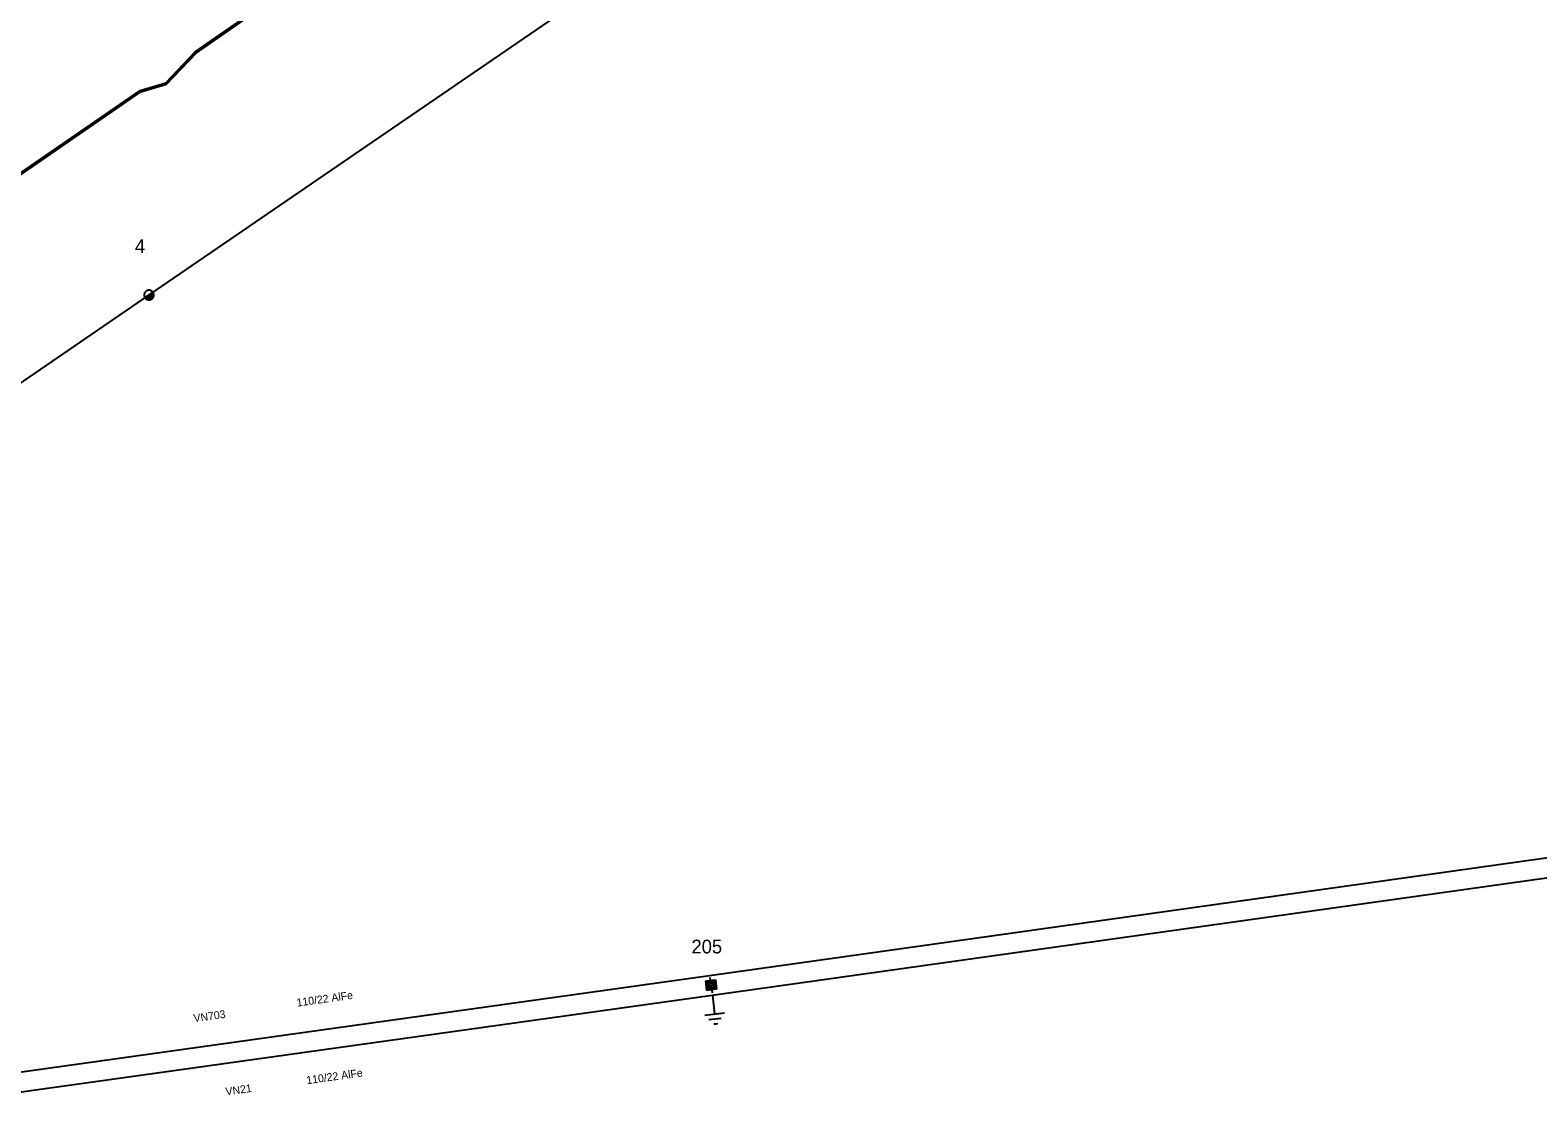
# Model space of a CAD drawing. Extents: x -545588 to -543214, y -1196037 to -1194452.
# Drawn here: x -545008.8 to -544817.1, y -1194901.6 to -1194764.6 of the extents above; entities that cross this region are included whole.
import ezdxf

# ---------------------------------------------------------------- set-up
doc = ezdxf.new("R2010")
doc.units = 0
for name, color, linetype in [('DOPLŇ_POPISY', 7, 'Continuous'), ('ELE_EON', 7, 'Continuous'), ('ELE_EON_POPIS', 7, 'Continuous'), ('POL_ZNAČKA_PRACOVNÍ', 7, 'Continuous'), ('SDEL_EON', 7, 'Continuous'), ('ZP_EON', 7, 'Continuous')]:
    doc.layers.add(name, color=color, linetype=linetype)

# ---------------------------------------------------------------- blocks, each defined once
blk = doc.blocks.new('VN440')
at = {"layer": 'ELE_EON_POPIS'}
for points in [[(1.22, 0), (1.21, 0.13), (1.19, 0.25), (1.16, 0.38), (1.11, 0.5), (1.05, 0.61), (0.98, 0.72), (0.9, 0.82), (0.81, 0.91), (0.71, 0.99), (0.6, 1.06), (0.49, 1.12), (0.37, 1.16), (0.25, 1.2), (0.12, 1.22), (-0.01, 1.22), (-0.14, 1.22), (-0.26, 1.2), (-0.39, 1.16), (-0.51, 1.12), (-0.62, 1.06), (-0.73, 0.99), (-0.83, 0.91), (-0.92, 0.82), (-1, 0.72), (-1.07, 0.61), (-1.13, 0.5), (-1.18, 0.38), (-1.21, 0.25), (-1.23, 0.13), (-1.24, 0), (-1.23, -0.13), (-1.21, -0.26), (-1.18, -0.38), (-1.13, -0.5), (-1.07, -0.62), (-1, -0.73), (-0.92, -0.83), (-0.83, -0.92), (-0.73, -1), (-0.62, -1.07), (-0.51, -1.13), (-0.39, -1.17), (-0.26, -1.2), (-0.14, -1.23), (-0.01, -1.23), (0.12, -1.23), (0.25, -1.2), (0.37, -1.17), (0.49, -1.13), (0.6, -1.07), (0.71, -1), (0.81, -0.92), (0.9, -0.83), (0.98, -0.73), (1.05, -0.62), (1.11, -0.5), (1.16, -0.38), (1.19, -0.26), (1.21, -0.13), (1.22, 0)], [(-1.24, 0), (1.22, 0)], [(-1.18, -0.34), (1.1, -0.34)], [(-1.01, -0.63), (0.97, -0.63)], [(-0.74, -0.92), (0.68, -0.92)]]:
    blk.add_lwpolyline(points, dxfattribs=at)
blk = doc.blocks.new('VN810')
at = {"layer": 'POL_ZNAČKA_PRACOVNÍ'}
for points in [[(0, -1.25), (0, -3.75)], [(1.25, -3.75), (-1.25, -3.75)], [(0.77, -4.37), (-0.8, -4.37)], [(0, -5), (-0.25, -5)], [(0.27, -5), (0, -5)]]:
    blk.add_lwpolyline(points, dxfattribs=at)
blk = doc.blocks.new('VN470')
at = {"layer": 'ELE_EON_POPIS'}
for points in [[(-1.23, 1.22), (1.23, 1.22)], [(-1.23, -1.23), (-1.23, 1.22)], [(-0.92, 0.9), (0.92, 0.9)], [(-0.92, -0.95), (-0.92, 0.9)], [(-0.61, 0.61), (0.61, 0.61)], [(-0.61, -0.62), (-0.61, 0.61)], [(-0.31, -0.27), (-0.31, 0.34)], [(-0.31, 0.34), (0.31, 0.34)], [(0, 1.22), (0, 1.97)], [(0.31, 0.34), (0.31, -0.27)], [(0.61, 0.61), (0.61, -0.62)], [(0.92, 0.9), (0.92, -0.95)], [(1.23, 1.22), (1.23, -1.23)], [(1.23, -1.23), (-1.23, -1.23)], [(0.92, -0.95), (-0.92, -0.95)], [(0.61, -0.62), (-0.61, -0.62)], [(0.31, -0.27), (-0.31, -0.27)], [(0, -1.23), (0, -1.98)]]:
    blk.add_lwpolyline(points, dxfattribs=at)

msp = doc.modelspace()

# ---------------------------------------------------------------- linework, layer by layer
at = {"layer": 'ELE_EON'}
for points in [[(-545096.16, -1194848.04), (-545075.95, -1194854.58), (-545032.81, -1194825.14), (-544993.69, -1194798.32), (-544903.01, -1194736.22), (-544804.37, -1194669.21), (-544702.68, -1194600.1), (-544611.95, -1194519.78), (-544514.29, -1194451.62)], [(-544083.88, -1194767.33), (-544137.68, -1194774.97), (-544275.32, -1194794.17), (-544399.3, -1194811.66), (-544539.71, -1194831.51), (-544666.5, -1194849.29), (-544797.03, -1194867.27), (-544922.4, -1194884.94), (-545023.84, -1194899.15), (-545076.33, -1194876.03), (-545112.81, -1194859.66)], [(-545068.16, -1194888.91), (-545023.6, -1194901.6), (-544922.06, -1194887.4), (-544796.64, -1194869.77), (-544666.32, -1194851.78), (-544539.47, -1194833.99), (-544398.96, -1194814.1), (-544275.11, -1194796.62), (-544137.43, -1194777.48), (-544081.81, -1194769.58)]]:
    msp.add_lwpolyline(points, dxfattribs=at)
at = {"layer": 'ZP_EON'}
for points in [[(-545017.49, -1194788.17), (-544994.72, -1194772.48), (-544991.46, -1194771.51), (-544987.68, -1194767.54), (-544970.83, -1194755.78), (-544959.36, -1194747.87), (-544955.67, -1194746.06), (-544943.12, -1194736.64), (-544921.55, -1194722), (-544915.88, -1194718.94), (-544907.79, -1194712.62), (-544897.27, -1194705.22), (-544885.19, -1194696.78), (-544879.36, -1194692.94), (-544877.31, -1194691.66), (-544872.77, -1194688.49), (-544862.92, -1194681.87), (-544849.13, -1194672.11), (-544823.19, -1194654.37), (-544796.58, -1194635.96)], [(-545233.41, -1194894.88), (-545178.88, -1194890.69), (-545165.68, -1194889.55), (-545162.68, -1194888.62), (-545146.55, -1194877.89), (-545122.2, -1194861.06), (-545095.47, -1194842.73), (-545060.25, -1194817.94), (-545034.96, -1194800.14), (-545017.61, -1194788.01), (-544994.8, -1194772.3), (-544991.56, -1194771.33), (-544987.81, -1194767.38), (-544970.95, -1194755.62), (-544959.46, -1194747.69), (-544955.77, -1194745.88), (-544943.24, -1194736.48), (-544921.65, -1194721.82), (-544915.98, -1194718.78), (-544907.91, -1194712.46), (-544897.39, -1194705.06), (-544885.31, -1194696.62), (-544879.55, -1194692.83), (-544879.87, -1194692.29)]]:
    msp.add_lwpolyline(points, dxfattribs=at)

# ---------------------------------------------------------------- block references
at = {"layer": 'DOPLŇ_POPISY'}
for name, p, xscale, yscale, rotation in [('VN440', (-544993.69, -1194798.32), 0.5, 0.5, 34.434347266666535), ('VN470', (-544922.19, -1194886.1), 0.49999999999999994, 0.4999999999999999, 6.796644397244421)]:
    msp.add_blockref(name, p, dxfattribs=dict(at, xscale=xscale, yscale=yscale, rotation=rotation))
at = {"layer": 'POL_ZNAČKA_PRACOVNÍ', "rotation": 6.791966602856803}
msp.add_blockref('VN810', (-544922.19, -1194886.1), dxfattribs=at)

# ---------------------------------------------------------------- texts
at = {"layer": 'ELE_EON_POPIS'}
for rotation, p in [(7.976, (-544974.84, -1194888.85)), (7.963, (-544973.6, -1194898.72))]:
    msp.add_text('110/22 AlFe', height=1, rotation=rotation, dxfattribs=at).set_placement(p)
at = {"layer": 'POL_ZNAČKA_PRACOVNÍ'}
for s, p in [('4', (-544995.48, -1194792.98)), ('205', (-544924.7, -1194882.08))]:
    msp.add_text(s, height=1.75, dxfattribs=at).set_placement(p)
at = {"layer": 'SDEL_EON'}
for s, rotation, p in [('VN703', 7.976, (-544987.95, -1194890.84)), ('VN21', 7.963, (-544983.88, -1194900.16))]:
    msp.add_text(s, height=1, rotation=rotation, dxfattribs=at).set_placement(p)

doc.saveas('drawing.dxf')
